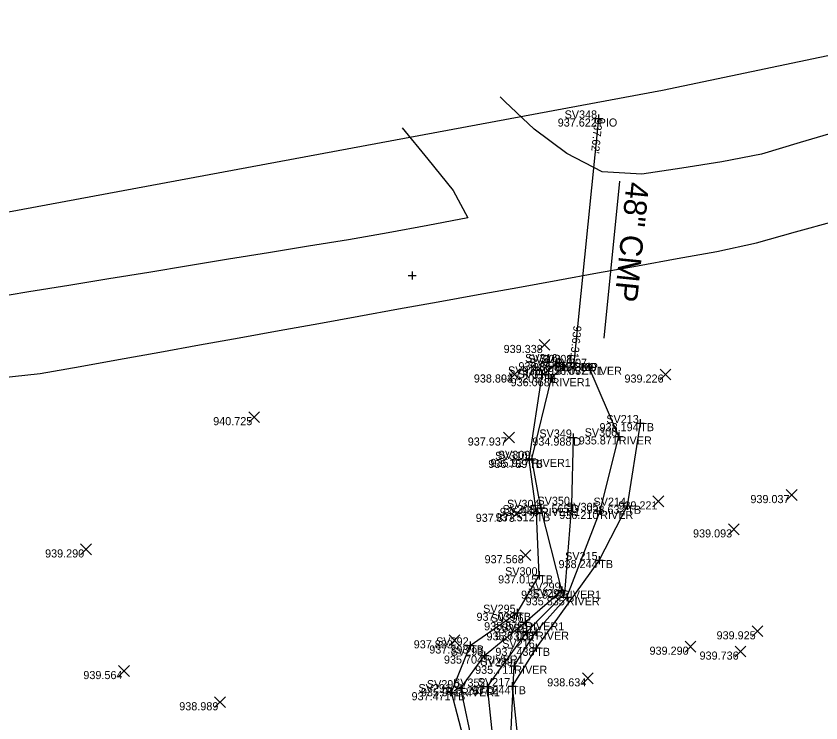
# Model space of a CAD drawing. Extents: x 2262025 to 2264532, y 740981 to 742724.
# Drawn here: x 2263114.1 to 2263213.5, y 742510 to 742597.4 of the extents above; entities that cross this region are included whole.
import ezdxf

# ---------------------------------------------------------------- set-up
doc = ezdxf.new("R2010")
doc.units = 0
for name, color, linetype in [('DR_X_Storm_Sewer', 7, 'Continuous'), ('DR_X_Text', 7, 'Continuous'), ('GE_X_Alignment_1000_Stations', 7, 'Continuous'), ('GE_X_Alignment_100_Distances', 7, 'Continuous'), ('GE_X_Alignment_500_Cardinal_Points', 7, 'Continuous'), ('GE_X_Alignment_500_Distances', 7, 'Continuous'), ('HY_X_Spring_Cells', 7, 'Continuous'), ('PV_X_Driveway', 7, 'Continuous'), ('RS_Raster1', 7, 'Continuous'), ('RW_X_CL', 7, 'Continuous'), ('RW_X_CL_100_Cardinal_Points', 7, 'Continuous'), ('RW_X_CL_500_Bearings', 7, 'Continuous'), ('SV_X_Text_Comment', 7, 'Continuous')]:
    doc.layers.add(name, color=color, linetype=linetype)

msp = doc.modelspace()

# ---------------------------------------------------------------- linework, layer by layer
at = {"layer": 'DR_X_Storm_Sewer'}
msp.add_line((2263186.061, 742584.76), (2263182.998, 742554.524), dxfattribs=at)
at = {"layer": 'DR_X_Text'}
msp.add_line((2263186.727, 742557.599), (2263188.694, 742577.02), dxfattribs=at)
at = {"layer": 'GE_X_Alignment_1000_Stations'}
for points in [[(2263156.54, 742465.462), (2263159.511, 742472.408), (2263162.283, 742482.293), (2263171.709, 742496.927), (2263169.765, 742506.568), (2263167.882, 742513.814), (2263170.183, 742519.594), (2263176.009, 742523.639), (2263178.705, 742528.264), (2263178.383, 742535.952), (2263177.466, 742542.542), (2263179.069, 742553.1), (2263181.182, 742554.627)], [(2263191.208, 742547.087), (2263189.607, 742536.874), (2263186.137, 742530.153), (2263178.357, 742519.307), (2263175.366, 742514.556), (2263176.338, 742505.44), (2263174.981, 742494.539), (2263171.435, 742480.576)]]:
    msp.add_lwpolyline(points, dxfattribs=at)
at = {"layer": 'GE_X_Alignment_100_Distances'}
msp.add_lwpolyline([(2263182.926, 742545.304), (2263182.707, 742536.985), (2263181.841, 742525.999), (2263177.145, 742521.221), (2263172.268, 742514.501), (2263173.34, 742504.299), (2263174.107, 742497.282), (2263173.098, 742495.112)], dxfattribs=at)
at = {"layer": 'GE_X_Alignment_500_Cardinal_Points'}
for p, q in [((2263178.712, 742556.091), (2263180.046, 742557.426)), ((2263178.712, 742557.426), (2263180.046, 742556.091)), ((2263175.002, 742552.44), (2263176.336, 742553.775)), ((2263175.002, 742553.775), (2263176.336, 742552.44)), ((2263193.656, 742552.432), (2263194.99, 742553.767)), ((2263193.656, 742553.767), (2263194.99, 742552.432)), ((2263142.827, 742547.163), (2263144.161, 742548.498)), ((2263142.827, 742548.498), (2263144.161, 742547.163)), ((2263174.321, 742544.645), (2263175.655, 742545.98)), ((2263174.321, 742545.98), (2263175.655, 742544.645)), ((2263209.256, 742537.526), (2263210.59, 742538.861)), ((2263209.256, 742538.861), (2263210.59, 742537.526)), ((2263192.779, 742536.745), (2263194.113, 742538.08)), ((2263192.779, 742538.08), (2263194.113, 742536.745)), ((2263175.254, 742535.214), (2263176.588, 742536.549)), ((2263175.254, 742536.549), (2263176.588, 742535.214)), ((2263202.111, 742533.284), (2263203.445, 742534.619)), ((2263202.111, 742534.619), (2263203.445, 742533.284)), ((2263122.04, 742530.807), (2263123.374, 742532.142)), ((2263122.04, 742532.142), (2263123.374, 742530.807)), ((2263176.358, 742530.092), (2263177.692, 742531.427)), ((2263176.358, 742531.427), (2263177.692, 742530.092)), ((2263205.043, 742520.681), (2263206.377, 742522.016)), ((2263205.043, 742522.016), (2263206.377, 742520.681)), ((2263167.591, 742519.565), (2263168.925, 742520.9)), ((2263167.591, 742520.9), (2263168.925, 742519.565)), ((2263196.749, 742518.778), (2263198.083, 742520.113)), ((2263196.749, 742520.113), (2263198.083, 742518.778)), ((2263202.933, 742518.174), (2263204.267, 742519.509)), ((2263202.933, 742519.509), (2263204.267, 742518.174)), ((2263126.74, 742515.764), (2263128.074, 742517.099)), ((2263126.74, 742517.099), (2263128.074, 742515.764)), ((2263184.069, 742514.864), (2263185.403, 742516.199)), ((2263184.069, 742516.199), (2263185.403, 742514.864)), ((2263138.603, 742511.906), (2263139.937, 742513.241)), ((2263138.603, 742513.241), (2263139.937, 742511.906))]:
    msp.add_line(p, q, dxfattribs=at)
at = {"layer": 'GE_X_Alignment_500_Distances'}
for points in [[(2263146.978, 742444.995), (2263154.374, 742458.669), (2263161.118, 742477.794), (2263167.063, 742486.076), (2263172.072, 742496.747), (2263170.651, 742506.723), (2263169.042, 742514.306), (2263171.973, 742518.345), (2263176.98, 742522.464), (2263181.532, 742526.377), (2263178.92, 742536.604), (2263177.792, 742542.662), (2263180.244, 742552.647), (2263181.73, 742554.073)], [(2263152.856, 742442.472), (2263157.93, 742457.814), (2263164.22, 742476.206), (2263166.175, 742482.748), (2263170.273, 742481.526), (2263170.85, 742485.887), (2263175.127, 742495.598), (2263175.171, 742507.454), (2263175.63, 742517.086), (2263178.312, 742521.294), (2263182.113, 742525.557), (2263186.262, 742536.231), (2263188.544, 742545.45), (2263184.86, 742554.06)]]:
    msp.add_lwpolyline(points, dxfattribs=at)
at = {"layer": 'PV_X_Driveway'}
for points in [[(2263268.654, 742598.297), (2263263.837, 742596.959), (2263259.019, 742595.62), (2263254.202, 742594.282), (2263249.384, 742592.943), (2263244.567, 742591.605), (2263239.749, 742590.266), (2263234.931, 742588.928), (2263230.14, 742587.5), (2263225.348, 742586.07), (2263220.557, 742584.641), (2263215.856, 742583.239), (2263210.974, 742581.783), (2263206.183, 742580.353), (2263201.287, 742579.389), (2263196.345, 742578.632), (2263191.402, 742577.875), (2263186.516, 742578.158), (2263182.112, 742580.433), (2263178.105, 742583.424), (2263174.483, 742586.867), (2263173.905, 742587.425)], [(2263161.796, 742583.598), (2263164.949, 742579.718), (2263168.101, 742575.837), (2263169.884, 742572.458), (2263164.97, 742571.533), (2263160.057, 742570.607), (2263155.128, 742569.767), (2263150.194, 742568.96), (2263145.259, 742568.153), (2263140.325, 742567.346), (2263135.39, 742566.539), (2263130.456, 742565.731), (2263125.522, 742564.924), (2263120.587, 742564.117), (2263115.653, 742563.31), (2263110.718, 742562.503), (2263105.751, 742561.935), (2263100.782, 742561.373), (2263095.814, 742560.812), (2263090.846, 742560.25), (2263085.877, 742559.688), (2263081.138, 742559.153)], [(2263112.073, 742552.671), (2263117.04, 742553.244), (2263121.968, 742554.08), (2263126.729, 742554.942), (2263131.809, 742555.861), (2263136.729, 742556.751), (2263141.649, 742557.641), (2263146.569, 742558.532), (2263151.489, 742559.422), (2263156.409, 742560.312), (2263161.329, 742561.203), (2263166.249, 742562.093), (2263171.169, 742562.983), (2263176.089, 742563.873), (2263181.01, 742564.764), (2263185.93, 742565.654), (2263190.85, 742566.544), (2263195.77, 742567.435), (2263200.69, 742568.325), (2263205.569, 742569.393), (2263210.387, 742570.731), (2263215.205, 742572.068)]]:
    msp.add_lwpolyline(points, dxfattribs=at)
at = {"layer": 'RS_Raster1'}
msp.add_lwpolyline([(2263811.079, 742440.009), (2263450.034, 742441.81), (2263472.225, 742554.627), (2263474.024, 742594.233), (2263511.208, 742683.646), (2263410.451, 742724.453), (2263373.867, 742626.038), (2263193.944, 742588.232), (2263081.193, 742567.229), (2263085.99, 742531.223), (2263114.178, 742392.602), (2262376.343, 742066.056)], dxfattribs=at)
at = {"layer": 'RW_X_CL_100_Cardinal_Points'}
for p, q in [((2263162.528, 742565.352), (2263163.528, 742565.352)), ((2263163.028, 742565.852), (2263163.028, 742564.852)), ((2263163.028, 742565.352), (2263163.028, 742565.352)), ((2263181.182, 742555.127), (2263181.182, 742554.127)), ((2263182.998, 742555.024), (2263182.998, 742554.024)), ((2263180.682, 742554.627), (2263181.682, 742554.627)), ((2263181.182, 742554.627), (2263181.182, 742554.627)), ((2263181.23, 742554.073), (2263182.23, 742554.073)), ((2263181.73, 742554.573), (2263181.73, 742553.573)), ((2263181.73, 742554.073), (2263181.73, 742554.073)), ((2263182.498, 742554.524), (2263183.498, 742554.524)), ((2263182.998, 742554.524), (2263182.998, 742554.524)), ((2263184.36, 742554.06), (2263185.36, 742554.06)), ((2263184.86, 742554.56), (2263184.86, 742553.56)), ((2263184.86, 742554.06), (2263184.86, 742554.06)), ((2263178.569, 742553.1), (2263179.569, 742553.1)), ((2263179.069, 742553.6), (2263179.069, 742552.6)), ((2263179.069, 742553.1), (2263179.069, 742553.1)), ((2263180.244, 742553.147), (2263180.244, 742552.147)), ((2263179.744, 742552.647), (2263180.744, 742552.647)), ((2263180.244, 742552.647), (2263180.244, 742552.647)), ((2263190.708, 742547.087), (2263191.708, 742547.087)), ((2263191.208, 742547.587), (2263191.208, 742546.587)), ((2263191.208, 742547.087), (2263191.208, 742547.087)), ((2263182.426, 742545.304), (2263183.426, 742545.304)), ((2263182.926, 742545.804), (2263182.926, 742544.804)), ((2263182.926, 742545.304), (2263182.926, 742545.304)), ((2263188.044, 742545.45), (2263189.044, 742545.45)), ((2263188.544, 742545.95), (2263188.544, 742544.95)), ((2263188.544, 742545.45), (2263188.544, 742545.45)), ((2263177.792, 742543.162), (2263177.792, 742542.162)), ((2263176.966, 742542.542), (2263177.966, 742542.542)), ((2263177.292, 742542.662), (2263178.292, 742542.662)), ((2263177.466, 742543.042), (2263177.466, 742542.042)), ((2263177.466, 742542.542), (2263177.466, 742542.542)), ((2263177.792, 742542.662), (2263177.792, 742542.662)), ((2263178.92, 742537.104), (2263178.92, 742536.104)), ((2263182.707, 742537.485), (2263182.707, 742536.485)), ((2263189.607, 742537.374), (2263189.607, 742536.374)), ((2263178.383, 742536.452), (2263178.383, 742535.452)), ((2263178.42, 742536.604), (2263179.42, 742536.604)), ((2263178.92, 742536.604), (2263178.92, 742536.604)), ((2263182.207, 742536.985), (2263183.207, 742536.985)), ((2263182.707, 742536.985), (2263182.707, 742536.985)), ((2263185.762, 742536.231), (2263186.762, 742536.231)), ((2263186.262, 742536.731), (2263186.262, 742535.731)), ((2263186.262, 742536.231), (2263186.262, 742536.231)), ((2263189.107, 742536.874), (2263190.107, 742536.874)), ((2263189.607, 742536.874), (2263189.607, 742536.874)), ((2263177.883, 742535.952), (2263178.883, 742535.952)), ((2263178.383, 742535.952), (2263178.383, 742535.952)), ((2263185.637, 742530.153), (2263186.637, 742530.153)), ((2263186.137, 742530.653), (2263186.137, 742529.653)), ((2263186.137, 742530.153), (2263186.137, 742530.153)), ((2263178.205, 742528.264), (2263179.205, 742528.264)), ((2263178.705, 742528.764), (2263178.705, 742527.764)), ((2263178.705, 742528.264), (2263178.705, 742528.264)), ((2263181.032, 742526.377), (2263182.032, 742526.377)), ((2263181.532, 742526.877), (2263181.532, 742525.877)), ((2263181.532, 742526.377), (2263181.532, 742526.377)), ((2263181.613, 742525.557), (2263182.613, 742525.557)), ((2263182.113, 742526.057), (2263182.113, 742525.057)), ((2263182.113, 742525.557), (2263182.113, 742525.557)), ((2263175.509, 742523.639), (2263176.509, 742523.639)), ((2263176.009, 742524.139), (2263176.009, 742523.139)), ((2263176.009, 742523.639), (2263176.009, 742523.639)), ((2263176.48, 742522.464), (2263177.48, 742522.464)), ((2263176.98, 742522.964), (2263176.98, 742521.964)), ((2263176.98, 742522.464), (2263176.98, 742522.464)), ((2263176.645, 742521.221), (2263177.645, 742521.221)), ((2263177.145, 742521.721), (2263177.145, 742520.721)), ((2263177.145, 742521.221), (2263177.145, 742521.221)), ((2263177.812, 742521.294), (2263178.812, 742521.294)), ((2263178.312, 742521.794), (2263178.312, 742520.794)), ((2263178.312, 742521.294), (2263178.312, 742521.294)), ((2263169.683, 742519.594), (2263170.683, 742519.594)), ((2263170.183, 742520.094), (2263170.183, 742519.094)), ((2263170.183, 742519.594), (2263170.183, 742519.594)), ((2263177.857, 742519.307), (2263178.857, 742519.307)), ((2263178.357, 742519.807), (2263178.357, 742518.807)), ((2263178.357, 742519.307), (2263178.357, 742519.307)), ((2263171.473, 742518.345), (2263172.473, 742518.345)), ((2263171.973, 742518.845), (2263171.973, 742517.845)), ((2263171.973, 742518.345), (2263171.973, 742518.345)), ((2263175.63, 742517.586), (2263175.63, 742516.586)), ((2263175.13, 742517.086), (2263176.13, 742517.086)), ((2263175.63, 742517.086), (2263175.63, 742517.086)), ((2263167.882, 742514.314), (2263167.882, 742513.314)), ((2263168.542, 742514.306), (2263169.542, 742514.306)), ((2263169.042, 742514.806), (2263169.042, 742513.806)), ((2263169.042, 742514.306), (2263169.042, 742514.306)), ((2263171.768, 742514.501), (2263172.768, 742514.501)), ((2263172.268, 742515.001), (2263172.268, 742514.001)), ((2263172.268, 742514.501), (2263172.268, 742514.501)), ((2263174.866, 742514.556), (2263175.866, 742514.556)), ((2263175.366, 742515.056), (2263175.366, 742514.056)), ((2263175.366, 742514.556), (2263175.366, 742514.556)), ((2263167.382, 742513.814), (2263168.382, 742513.814)), ((2263167.882, 742513.814), (2263167.882, 742513.814))]:
    msp.add_line(p, q, dxfattribs=at)
at = {"layer": 'RW_X_CL_500_Bearings'}
for p, q in [((2263186.061, 742585.26), (2263186.061, 742584.26)), ((2263186.061, 742585.26), (2263186.061, 742584.26)), ((2263185.561, 742584.76), (2263186.561, 742584.76)), ((2263185.561, 742584.76), (2263186.561, 742584.76)), ((2263186.061, 742584.76), (2263186.061, 742584.76)), ((2263186.061, 742584.76), (2263186.061, 742584.76)), ((2263182.998, 742555.024), (2263182.998, 742554.024)), ((2263182.998, 742555.024), (2263182.998, 742554.024)), ((2263182.498, 742554.524), (2263183.498, 742554.524)), ((2263182.498, 742554.524), (2263183.498, 742554.524)), ((2263182.998, 742554.524), (2263182.998, 742554.524)), ((2263182.998, 742554.524), (2263182.998, 742554.524))]:
    msp.add_line(p, q, dxfattribs=at)

# ---------------------------------------------------------------- texts
at = {"layer": 'DR_X_Text'}
msp.add_text('48" CMP', height=2.8, rotation=264.21549, dxfattribs=at).set_placement((2263189.52, 742576.996))
at = {"layer": 'HY_X_Spring_Cells'}
for s, p in [('937.622', (2263181.005, 742583.76)), ('937.622', (2263181.005, 742583.76)), ('939.338', (2263174.32, 742555.758)), ('936.854', (2263176.151, 742553.627)), ('936.018', (2263176.671, 742553.073)), ('936.312', (2263177.942, 742553.524)), ('936.312', (2263177.942, 742553.524)), ('936.312', (2263177.942, 742553.524)), ('936.032', (2263179.804, 742553.06)), ('938.804', (2263170.638, 742552.107)), ('937.205', (2263173.998, 742552.1)), ('939.226', (2263189.259, 742552.099)), ('936.068', (2263175.185, 742551.647)), ('940.725', (2263138.423, 742546.83)), ('938.194', (2263186.177, 742546.087)), ('937.937', (2263169.885, 742544.312)), ('934.988', (2263177.867, 742544.304)), ('935.871', (2263183.603, 742544.45)), ('936.789', (2263172.425, 742541.542)), ('935.927', (2263172.689, 742541.662)), ('939.037', (2263204.82, 742537.193)), ('939.221', (2263188.505, 742536.412)), ('935.940', (2263173.859, 742535.604)), ('935.565', (2263177.636, 742535.985)), ('936.210', (2263181.201, 742535.231)), ('938.632', (2263184.551, 742535.874)), ('937.873', (2263170.871, 742534.881)), ('937.512', (2263173.327, 742534.952)), ('939.093', (2263197.728, 742532.951)), ('939.290', (2263117.646, 742530.474)), ('937.568', (2263171.966, 742529.759)), ('938.244', (2263181.106, 742529.153)), ('937.015', (2263173.634, 742527.264)), ('935.948', (2263176.473, 742525.377)), ('935.835', (2263177.042, 742524.557)), ('937.039', (2263170.968, 742522.639)), ('935.875', (2263171.909, 742521.464)), ('935.731', (2263172.204, 742520.221)), ('936.058', (2263173.253, 742520.294)), ('939.925', (2263200.639, 742520.348)), ('937.833', (2263163.208, 742519.232)), ('937.393', (2263165.133, 742518.594)), ('937.438', (2263173.298, 742518.307)), ('939.290', (2263192.355, 742518.445)), ('935.704', (2263166.942, 742517.345)), ('939.736', (2263198.536, 742517.841)), ('939.564', (2263122.376, 742515.431)), ('935.711', (2263170.793, 742516.086)), ('938.634', (2263179.705, 742514.531)), ('935.971', (2263164.101, 742513.306)), ('935.267', (2263167.165, 742513.501)), ('937.244', (2263170.335, 742513.556)), ('937.471', (2263162.941, 742512.814)), ('938.989', (2263134.229, 742511.573))]:
    msp.add_text(s, height=1, dxfattribs=at).set_placement(p)
at = {"layer": 'RS_Raster1'}
for s, p in [("937.62'", (2263185.564, 742584.81)), ("936.31'", (2263182.967, 742559.183))]:
    msp.add_text(s, height=1, rotation=264.21549, dxfattribs=at).set_placement(p)
at = {"layer": 'RW_X_CL'}
for s, p in [('PIO', (2263186.061, 742583.76)), ('PIO', (2263186.061, 742583.76)), ('TB', (2263181.182, 742553.627)), ('RIVER1', (2263181.73, 742553.073)), ('CMP', (2263182.998, 742553.524)), ('PIO', (2263182.998, 742553.524)), ('FDO', (2263182.998, 742553.524)), ('RIVER', (2263184.86, 742553.06)), ('TB', (2263179.069, 742552.1)), ('RIVER1', (2263180.244, 742551.647)), ('TB', (2263191.208, 742546.087)), ('D', (2263182.926, 742544.304)), ('RIVER', (2263188.544, 742544.45)), ('TB', (2263177.466, 742541.542)), ('RIVER1', (2263177.792, 742541.662)), ('RIVER1', (2263178.92, 742535.604)), ('D', (2263182.707, 742535.985)), ('RIVER', (2263186.262, 742535.231)), ('TB', (2263189.607, 742535.874)), ('TB', (2263178.383, 742534.952)), ('TB', (2263186.137, 742529.153)), ('TB', (2263178.705, 742527.264)), ('RIVER1', (2263181.532, 742525.377)), ('RIVER', (2263182.113, 742524.557)), ('TB', (2263176.009, 742522.639)), ('RIVER1', (2263176.98, 742521.464)), ('D', (2263177.145, 742520.221)), ('RIVER', (2263178.312, 742520.294)), ('TB', (2263170.183, 742518.594)), ('TB', (2263178.357, 742518.307)), ('RIVER1', (2263171.973, 742517.345)), ('RIVER', (2263175.63, 742516.086)), ('RIVER1', (2263169.042, 742513.306)), ('D', (2263172.268, 742513.501)), ('TB', (2263175.366, 742513.556)), ('TB', (2263167.882, 742512.814))]:
    msp.add_text(s, height=1, dxfattribs=at).set_placement(p)
at = {"layer": 'SV_X_Text_Comment'}
for s, p in [('SV348', (2263181.855, 742584.76)), ('SV348', (2263181.855, 742584.76)), ('SV316', (2263176.972, 742554.627)), ('SV308_1', (2263177.358, 742554.524)), ('SV315', (2263177.513, 742554.073)), ('SV308', (2263178.792, 742554.524)), ('SV308', (2263178.792, 742554.524)), ('SV307', (2263180.611, 742554.06)), ('SV313', (2263174.873, 742553.1)), ('SV314', (2263176.066, 742552.647)), ('SV213', (2263187.012, 742547.087)), ('SV349', (2263178.738, 742545.304)), ('SV306', (2263184.334, 742545.45)), ('SV310', (2263173.259, 742542.542)), ('SV309', (2263173.604, 742542.662)), ('SV304', (2263174.742, 742536.604)), ('SV350', (2263178.5, 742536.985)), ('SV305', (2263182.045, 742536.231)), ('SV214', (2263185.429, 742536.874)), ('SV303', (2263174.187, 742535.952)), ('SV215', (2263181.92, 742530.153)), ('SV300', (2263174.498, 742528.264)), ('SV299', (2263177.344, 742526.377)), ('SV298', (2263177.907, 742525.557)), ('SV295', (2263171.792, 742523.639)), ('SV296', (2263172.77, 742522.464)), ('SV351', (2263173.058, 742521.221)), ('SV297', (2263174.063, 742521.294)), ('SV292', (2263165.98, 742519.594)), ('SV216', (2263174.147, 742519.307)), ('SV293', (2263167.777, 742518.345)), ('SV289', (2263171.442, 742517.086)), ('SV290', (2263164.835, 742514.306)), ('SV352', (2263168.065, 742514.501)), ('SV217', (2263171.117, 742514.556)), ('SV291', (2263163.795, 742513.814))]:
    msp.add_text(s, height=1, dxfattribs=at).set_placement(p)

doc.saveas('drawing.dxf')
